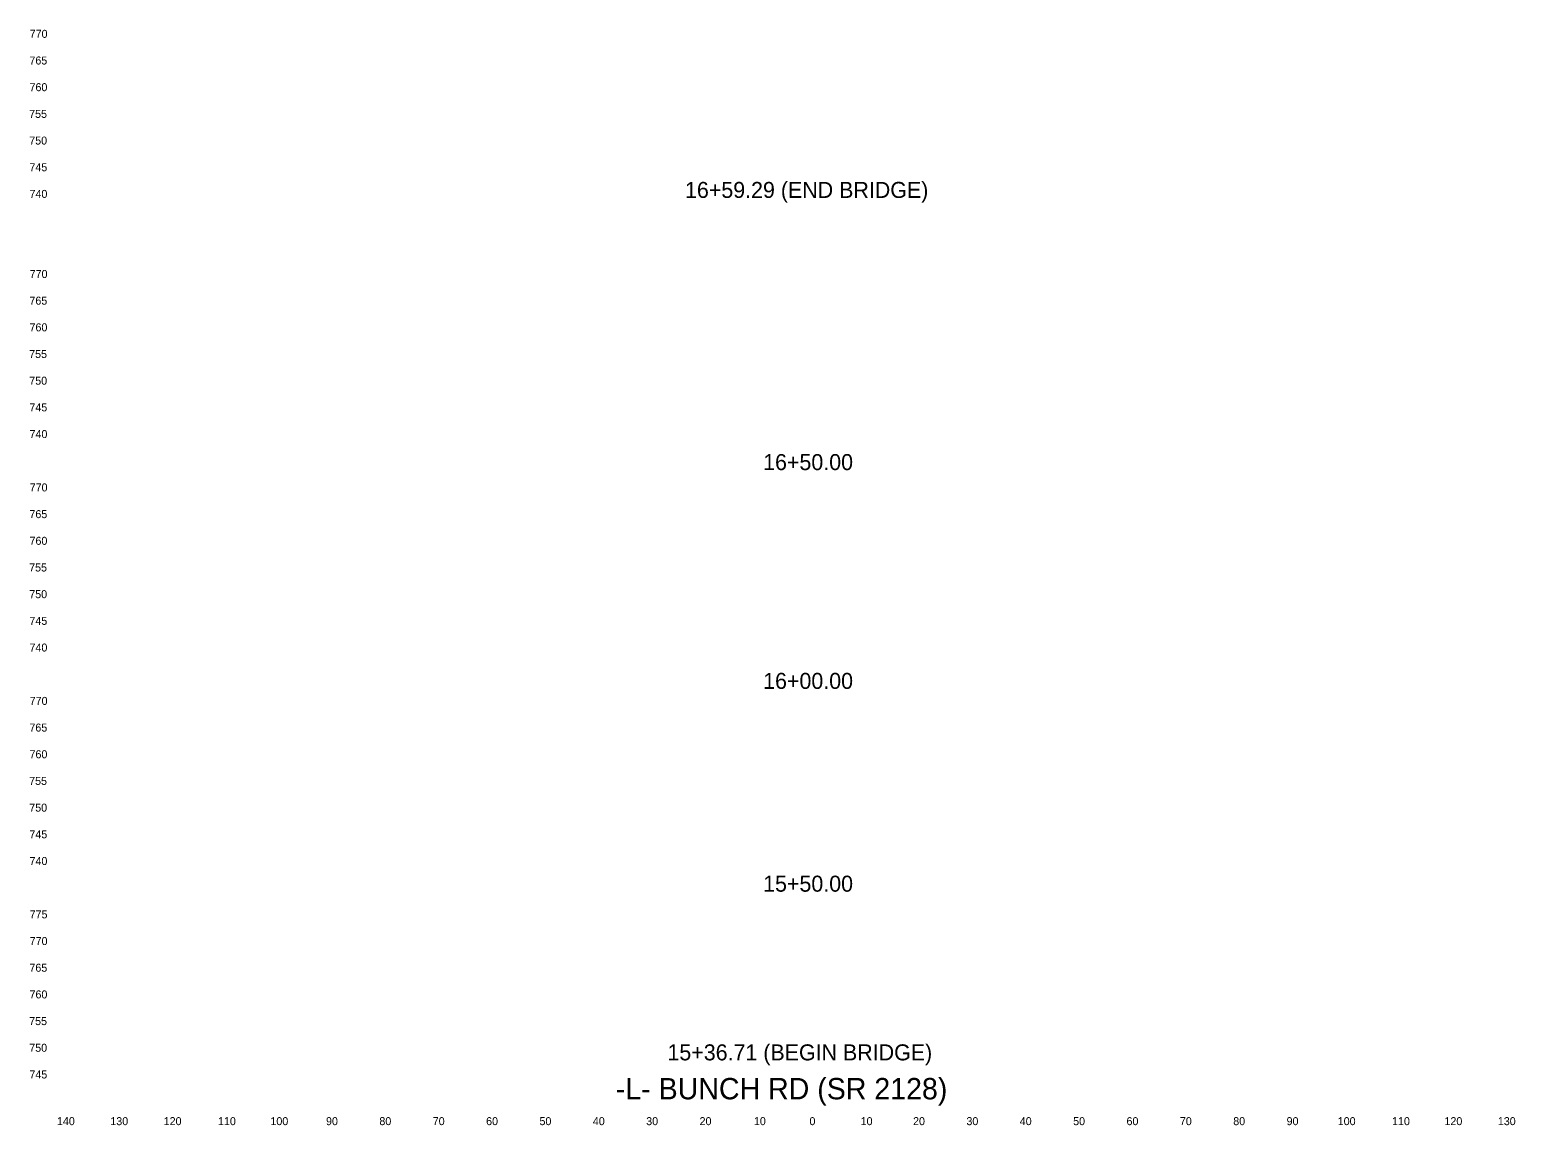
# Model space of a CAD drawing. Extents: x 2473106 to 2475402, y 633617 to 633851.
# Drawn here: x 2474309 to 2474587.4, y 633618.8 to 633824.1 of the extents above; entities that cross this region are included whole.
import ezdxf

# ---------------------------------------------------------------- set-up
doc = ezdxf.new("R2010")
doc.units = 0
for name, color, linetype in [('Exist Cross Section Cell', 7, 'Continuous'), ('Exist XS Center Line Elevation Label', 7, 'Continuous'), ('Exist XS Ground Line', 7, 'Continuous'), ('Scratch_Level_5', 7, 'Continuous')]:
    doc.layers.add(name, color=color, linetype=linetype)

msp = doc.modelspace()

# ---------------------------------------------------------------- texts
at = {"layer": 'Exist Cross Section Cell'}
for s, p in [('140', (2474314.13, 633618.82)), ('130', (2474324.13, 633618.82)), ('120', (2474334.13, 633618.82)), ('110', (2474344.31, 633618.82)), ('100', (2474354.13, 633618.82)), ('90', (2474364.55, 633618.82)), ('80', (2474374.55, 633618.82)), ('70', (2474384.55, 633618.82)), ('60', (2474394.55, 633618.82)), ('50', (2474404.55, 633618.82)), ('40', (2474414.55, 633618.82)), ('30', (2474424.55, 633618.82)), ('20', (2474434.55, 633618.82)), ('10', (2474444.73, 633618.82)), ('0', (2474455.14, 633618.82)), ('0', (2474455.14, 633618.82)), ('10', (2474464.73, 633618.82)), ('20', (2474474.55, 633618.82)), ('30', (2474484.55, 633618.82)), ('40', (2474494.55, 633618.82)), ('50', (2474504.55, 633618.82)), ('60', (2474514.55, 633618.82)), ('70', (2474524.55, 633618.82)), ('80', (2474534.55, 633618.82)), ('90', (2474544.55, 633618.82)), ('100', (2474554.13, 633618.82)), ('110', (2474564.31, 633618.82)), ('120', (2474574.13, 633618.82)), ('130', (2474584.13, 633618.82))]:
    msp.add_text(s, height=1.5, dxfattribs=at).set_placement(p)
at = {"layer": 'Exist XS Center Line Elevation Label'}
for s, p in [('16+59.29 (END BRIDGE)', (2474431.82, 633792.57)), ('16+50.00', (2474446.46, 633741.57)), ('16+00.00', (2474446.46, 633700.57)), ('15+50.00', (2474446.46, 633662.57)), ('15+36.71 (BEGIN BRIDGE)', (2474428.53, 633630.96))]:
    msp.add_text(s, height=3, dxfattribs=at).set_placement(p)
at = {"layer": 'Exist XS Ground Line'}
for s, p in [('770', (2474309.02, 633822.57)), ('765', (2474308.97, 633817.57)), ('760', (2474308.99, 633812.57)), ('755', (2474308.92, 633807.57)), ('750', (2474308.94, 633802.57)), ('745', (2474308.97, 633797.57)), ('740', (2474308.99, 633792.57)), ('770', (2474309.02, 633777.57)), ('765', (2474308.97, 633772.57)), ('760', (2474308.99, 633767.57)), ('755', (2474308.92, 633762.57)), ('750', (2474308.94, 633757.57)), ('745', (2474308.97, 633752.57)), ('740', (2474308.99, 633747.57)), ('770', (2474309.02, 633737.57)), ('765', (2474308.97, 633732.57)), ('760', (2474308.99, 633727.57)), ('755', (2474308.92, 633722.57)), ('750', (2474308.94, 633717.57)), ('745', (2474308.97, 633712.57)), ('740', (2474308.99, 633707.57)), ('770', (2474309.02, 633697.57)), ('765', (2474308.97, 633692.57)), ('760', (2474308.99, 633687.57)), ('755', (2474308.92, 633682.57)), ('750', (2474308.94, 633677.57)), ('745', (2474308.97, 633672.57)), ('740', (2474308.99, 633667.57)), ('775', (2474309.01, 633657.57)), ('770', (2474309.02, 633652.57)), ('765', (2474308.97, 633647.57)), ('760', (2474308.99, 633642.57)), ('755', (2474308.92, 633637.57)), ('750', (2474308.94, 633632.57)), ('745', (2474308.97, 633627.57))]:
    msp.add_text(s, height=1.5, dxfattribs=at).set_placement(p)
at = {"layer": 'Scratch_Level_5'}
msp.add_text('-L- BUNCH RD (SR 2128)', height=4, dxfattribs=at).set_placement((2474418.86, 633623.66))

doc.saveas('drawing.dxf')
